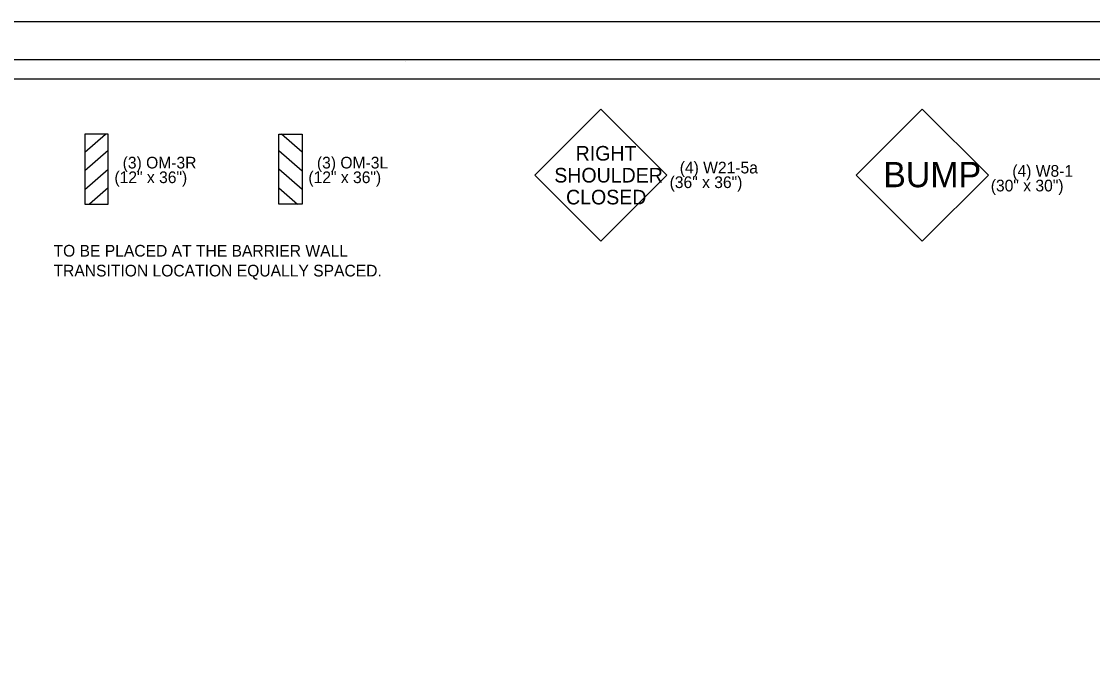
# Model space of a CAD drawing. Extents: x 1368648 to 1927880, y -1037443 to 380209.
# Drawn here: x 1370418 to 1370968, y 379428 to 379753 of the extents above; entities that cross this region are included whole.
import ezdxf

# ---------------------------------------------------------------- set-up
doc = ezdxf.new("R2010")
doc.units = 0
for name, color, linetype in [('Default', 7, 'Continuous'), ('R_Border', 7, 'Continuous'), ('R_No Plot', 7, 'Continuous'), ('R_Signs', 7, 'Continuous'), ('R_Signs_Annot', 7, 'Continuous')]:
    doc.layers.add(name, color=color, linetype=linetype)

msp = doc.modelspace()

# ---------------------------------------------------------------- linework, layer by layer
at = {"layer": 'R_Border'}
for p, q in [((1369852.42, 379733.26), (1371433.32, 379733.26)), ((1370615.02, 379731.96), (1370615.02, 379731.96)), ((1370615.02, 379731.96), (1370615.02, 379731.96))]:
    msp.add_line(p, q, dxfattribs=at)
at = {"layer": 'R_No Plot'}
for points in [[(1369790.38, 379752.73), (1371457.08, 379752.73), (1371457.08, 378686.04), (1369790.38, 378686.04)], [(1371423.32, 379229.61), (1369862.42, 379229.61), (1369862.42, 379723.26), (1371110.12, 379723.26), (1371110.12, 379673.86), (1371197.82, 379673.86), (1371318.32, 379673.86), (1371318.32, 379562.19), (1371423.32, 379562.19)], [(1369862.42, 379723.26), (1371110.12, 379723.26), (1371110.12, 379673.86), (1371197.82, 379673.86), (1371318.32, 379673.86), (1371318.32, 379562.19), (1371423.32, 379562.19), (1371423.32, 378715.96), (1369862.42, 378715.96)]]:
    msp.add_lwpolyline(points, close=True, dxfattribs=at)
at = {"layer": 'R_Signs'}
for p, q in [((1370715.23, 379707.73), (1370681.28, 379673.79)), ((1370749.15, 379673.79), (1370715.23, 379707.73)), ((1370880.23, 379707.73), (1370846.28, 379673.79)), ((1370914.17, 379673.79), (1370880.23, 379707.73)), ((1370681.28, 379673.79), (1370715.23, 379639.85)), ((1370715.23, 379639.85), (1370749.15, 379673.79)), ((1370846.28, 379673.79), (1370880.23, 379639.85)), ((1370880.23, 379639.85), (1370914.17, 379673.79))]:
    msp.add_line(p, q, dxfattribs=at)
for points in [[(1370462.32, 379694.86), (1370450.32, 379694.86), (1370450.32, 379658.86), (1370462.32, 379658.86)], [(1370460.98, 379694.86), (1370450.32, 379694.86), (1370450.32, 379685.58)], [(1370549.89, 379694.86), (1370561.89, 379694.86), (1370561.89, 379658.86), (1370549.89, 379658.86)], [(1370551.23, 379694.86), (1370561.89, 379694.86), (1370561.89, 379685.58)], [(1370462.32, 379676.85), (1370462.32, 379686.44), (1370450.32, 379675.98), (1370450.32, 379666.4)], [(1370549.89, 379676.85), (1370549.89, 379686.44), (1370561.89, 379675.98), (1370561.89, 379666.4)], [(1370462.32, 379658.86), (1370462.32, 379667.27), (1370452.68, 379658.86), (1370452.68, 379658.86)], [(1370549.89, 379658.86), (1370549.89, 379667.27), (1370559.54, 379658.86), (1370559.54, 379658.86)]]:
    msp.add_lwpolyline(points, close=True, dxfattribs=at)

# ---------------------------------------------------------------- texts
at = {"layer": 'Default'}
for s, p in [('TO BE PLACED AT THE BARRIER WALL', (1370434.27, 379632.01)), ('TRANSITION LOCATION EQUALLY SPACED.', (1370434.27, 379621.81))]:
    msp.add_text(s, height=6, dxfattribs=at).set_placement(p)
at = {"layer": 'R_Signs'}
for s, height, p in [('RIGHT', 7.5, (1370702.3, 379681.29)), ('BUMP', 13, (1370860.24, 379667.62)), ('SHOULDER', 7.5, (1370691.34, 379670.04)), ('CLOSED', 7.5, (1370697.38, 379658.79))]:
    msp.add_text(s, height=height, dxfattribs=at).set_placement(p)
at = {"layer": 'R_Signs_Annot'}
for s, p in [('(3) OM-3R', (1370469.76, 379677.24)), ('(3) OM-3L', (1370569.49, 379677.24)), ('(4) W21-5a', (1370755.74, 379674.7)), ('(12" x 36")', (1370465.53, 379669.73)), ('(12" x 36")', (1370565.1, 379669.73)), ('(4) W8-1', (1370926.48, 379672.98)), ('(36" x 36")', (1370750.55, 379667.19)), ('(30" x 30")', (1370915.42, 379665.47))]:
    msp.add_text(s, height=6, dxfattribs=at).set_placement(p)

doc.saveas('drawing.dxf')
